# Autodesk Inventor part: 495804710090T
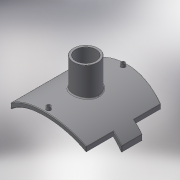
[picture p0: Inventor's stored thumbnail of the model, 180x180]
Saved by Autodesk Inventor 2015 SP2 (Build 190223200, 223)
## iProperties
Created: 2017-10
Part Number: 495804710090T
Material: Generic
Description: PLASSON BRANCH SADDLE 450-800X90
Document SubType Name: Modeling
Designer: KIM
Density: 1 g/cm^3
Appearance: Default
Author: KIM
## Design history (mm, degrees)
derived "495804 (SECOND).ipt"
feature "Solid1::495804 (SECOND).ipt"
tag "TaggingFeature1"
body "Solid1"
other parameters: "d1" = 15, "d2" = 283.5, "d4" = 0, "d5" = 315, "d6" = 75, "d7" = 0, "d8" = 135, "d10" = 0, "d11" = 4, "d12" = 425.6, "d13" = 14, "d14" = 135, "d16" = 5 deg, "d18" = 4, "d19" = 14, "d20" = 0, "d21" = 3, "d22" = 0, "d25" = 16, "d26" = 72, "d28" = 0, "d29" = 9.6, "d31" = 0, "d32" = 31.5, "d33" = 0, "d34" = 8, "d35" = 1.6, "B_" = 315, "H_" = 105, "x_" = 15, "D_" = 16
